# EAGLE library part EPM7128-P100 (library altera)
EPM70128 MAX 7000 family
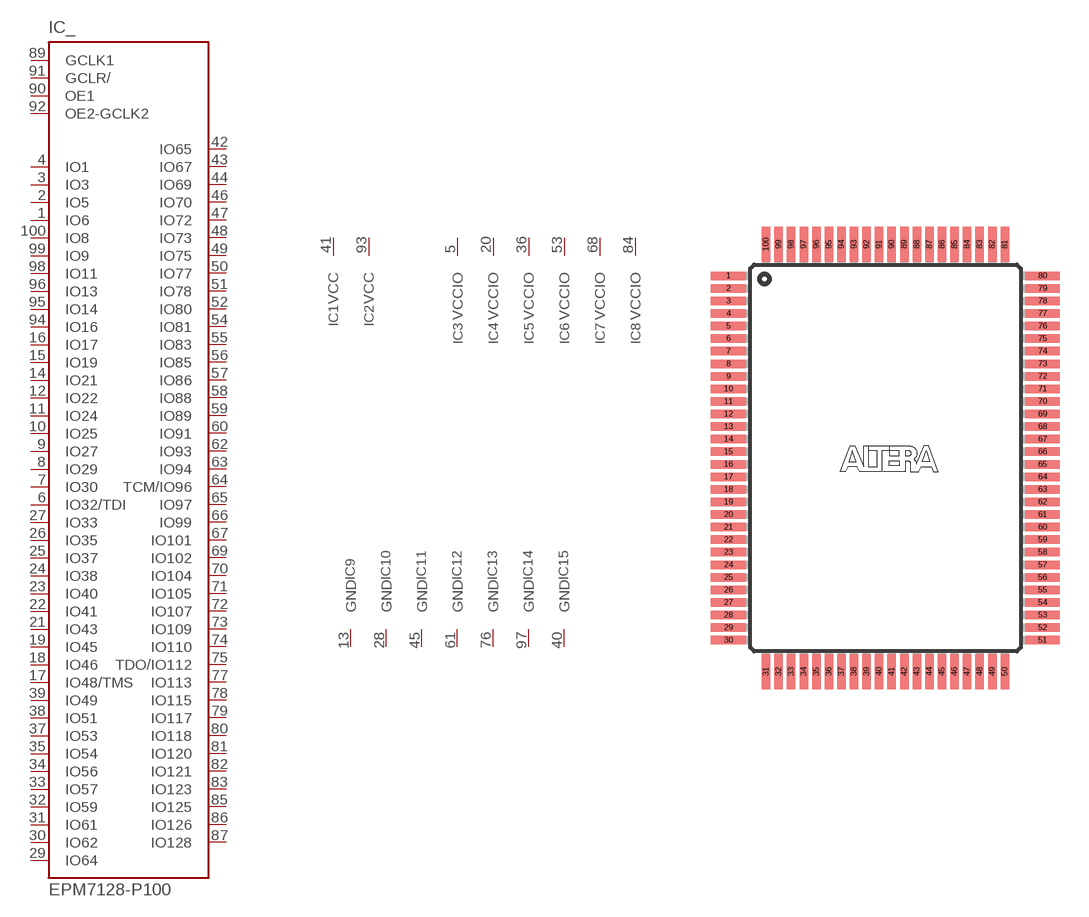
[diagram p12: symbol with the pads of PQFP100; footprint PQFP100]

Designator prefix IC; gates _=7128P100 1=VCC 2=VCC 3=VCCIO 4=VCCIO 5=VCCIO 6=VCCIO 7=VCCIO 8=VCCIO 9=GND 10=GND 11=GND 12=GND 13=GND 14=GND 15=GND 16=GND

## EPM7128-P100  [PQFP100]
1  _:IO6
2  _:IO5
3  _:IO3
4  _:IO1
5  3:VCCIO  pwr
6  _:IO32/TDI
7  _:IO30
8  _:IO29
9  _:IO27
10  _:IO25
11  _:IO24
12  _:IO22
13  9:GND  pwr
14  _:IO21
15  _:IO19
16  _:IO17
17  _:IO48/TMS
18  _:IO46
19  _:IO45
20  4:VCCIO  pwr
21  _:IO43
22  _:IO41
23  _:IO40
24  _:IO38
25  _:IO37
26  _:IO35
27  _:IO33
28  10:GND  pwr
29  _:IO64
30  _:IO62
31  _:IO61
32  _:IO59
33  _:IO57
34  _:IO56
35  _:IO54
36  5:VCCIO  pwr
37  _:IO53
38  _:IO51
39  _:IO49
40  15:GND  pwr
41  1:VCC  pwr
42  _:IO65
43  _:IO67
44  _:IO69
45  11:GND  pwr
46  _:IO70
47  _:IO72
48  _:IO73
49  _:IO75
50  _:IO77
51  _:IO78
52  _:IO80
53  6:VCCIO  pwr
54  _:IO81
55  _:IO83
56  _:IO85
57  _:IO86
58  _:IO88
59  _:IO89
60  _:IO91
61  12:GND  pwr
62  _:IO93
63  _:IO94
64  _:TCM/IO96
65  _:IO97
66  _:IO99
67  _:IO101
68  7:VCCIO  pwr
69  _:IO102
70  _:IO104
71  _:IO105
72  _:IO107
73  _:IO109
74  _:IO110
75  _:TDO/IO112
76  13:GND  pwr
77  _:IO113
78  _:IO115
79  _:IO117
80  _:IO118
81  _:IO120
82  _:IO121
83  _:IO123
84  8:VCCIO  pwr
85  _:IO125
86  _:IO126
87  _:IO128
88  16:GND  pwr
89  _:GCLK1  in
90  _:OE1  in
91  _:GCLR/  in
92  _:OE2-GCLK2  in
93  2:VCC  pwr
94  _:IO16
95  _:IO14
96  _:IO13
97  14:GND  pwr
98  _:IO11
99  _:IO9
100  _:IO8

## Footprint PQFP100 (pad centres in mm)
Plastic Quad Flat Pack
smd 1.8 x 0.44: 1 -8.125,9.425; 2 -8.125,8.775; 3 -8.125,8.125; 4 -8.125,7.475; 5 -8.125,6.825; 6 -8.125,6.175; 7 -8.125,5.525; 8 -8.125,4.875; 9 -8.125,4.225; 10 -8.125,3.575; 11 -8.125,2.925; 12 -8.125,2.275; 13 -8.125,1.625; 14 -8.125,0.975; 15 -8.125,0.325; 16 -8.125,-0.325; 17 -8.125,-0.975; 18 -8.125,-1.625; 19 -8.125,-2.275; 20 -8.125,-2.925; 21 -8.125,-3.575; 22 -8.125,-4.225; 23 -8.125,-4.875; 24 -8.125,-5.525; 25 -8.125,-6.175; 26 -8.125,-6.825; 27 -8.125,-7.475; 28 -8.125,-8.125; 29 -8.125,-8.775; 30 -8.125,-9.425; 51 8.125,-9.425; 52 8.125,-8.775; 53 8.125,-8.125; 54 8.125,-7.475; 55 8.125,-6.825; 56 8.125,-6.175; 57 8.125,-5.525; 58 8.125,-4.875; 59 8.125,-4.225; 60 8.125,-3.575; 61 8.125,-2.925; 62 8.125,-2.275; 63 8.125,-1.625; 64 8.125,-0.975; 65 8.125,-0.325; 66 8.125,0.325; 67 8.125,0.975; 68 8.125,1.625; 69 8.125,2.275; 70 8.125,2.925; 71 8.125,3.575; 72 8.125,4.225; 73 8.125,4.875; 74 8.125,5.525; 75 8.125,6.175; 76 8.125,6.825; 77 8.125,7.475; 78 8.125,8.125; 79 8.125,8.775; 80 8.125,9.425
smd 0.44 x 1.8: 31 -6.175,-11.05; 32 -5.525,-11.05; 33 -4.875,-11.05; 34 -4.225,-11.05; 35 -3.575,-11.05; 36 -2.925,-11.05; 37 -2.275,-11.05; 38 -1.625,-11.05; 39 -0.975,-11.05; 40 -0.325,-11.05; 41 0.325,-11.05; 42 0.975,-11.05; 43 1.625,-11.05; 44 2.275,-11.05; 45 2.925,-11.05; 46 3.575,-11.05; 47 4.225,-11.05; 48 4.875,-11.05; 49 5.525,-11.05; 50 6.175,-11.05; 81 6.175,11.05; 82 5.525,11.05; 83 4.875,11.05; 84 4.225,11.05; 85 3.575,11.05; 86 2.925,11.05; 87 2.275,11.05; 88 1.625,11.05; 89 0.975,11.05; 90 0.325,11.05; 91 -0.325,11.05; 92 -0.975,11.05; 93 -1.625,11.05; 94 -2.275,11.05; 95 -2.925,11.05; 96 -3.575,11.05; 97 -4.225,11.05; 98 -4.875,11.05; 99 -5.525,11.05; 100 -6.175,11.05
